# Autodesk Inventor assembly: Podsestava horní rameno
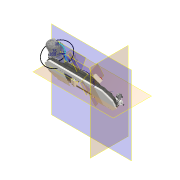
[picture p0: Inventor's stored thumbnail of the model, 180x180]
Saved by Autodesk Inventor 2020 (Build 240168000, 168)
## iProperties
Created: 2025-04
Part Number: Podsestava horní rameno
Document SubType Name: Assembly
Designer: doma
Mass: 92595.2 g
Surface Area: 37846.4 cm^2
Volume: 13606.3 cm^3
Density: 6.80533 g/cm^3
Author: doma
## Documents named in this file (61)
- C:\Users\doma\Desktop\Pásovka záloha\Workgroups\NotInProject\Podsestava horní rameno.iam
- C:\Users\doma\Desktop\Pásovka záloha\Workgroups\NotInProject\Svařenec rameno.iam
- C:\Users\doma\Desktop\Pásovka záloha\Workgroups\NotInProject\Svařenec čepu.iam
- C:\Users\doma\Desktop\Pásovka záloha\Workgroups\NotInProject\Vedení hnaného kola 1.ipt
- C:\Users\doma\Desktop\Pásovka záloha\Workgroups\NotInProject\Zajištění vedení.ipt
- C:\Users\doma\Documents\Inventor\Content Center Files\R2020\cs-CZ\CSN 024665 SKF (A)\CSN 024665 SKF (A) - SKF 3206 A.ipt
- C:\Users\doma\Desktop\Pásovka záloha\Workgroups\NotInProject\Kolo hnané.ipt
- C:\Users\doma\Desktop\Pásovka záloha\Workgroups\NotInProject\Náboj hnaného kola.ipt
- C:\Users\doma\Desktop\Pásovka záloha\Workgroups\NotInProject\Svařenec čepu hnaného kola.iam
- C:\Users\doma\Documents\Inventor\Content Center Files\R2020\cs-CZ\CSN 02 2931\CSN 02 2931 - 62.ipt
- C:\Users\doma\Desktop\Pásovka záloha\Workgroups\NotInProject\Zajištění ložiska kola.ipt
- C:\Users\doma\Desktop\Pásovka záloha\Workgroups\NotInProject\Svařenec hnacího kola.iam
- C:\Users\doma\Desktop\Pásovka záloha\Workgroups\NotInProject\Zajištění hnacího kola.ipt
- C:\Users\doma\Desktop\Pásovka záloha\Workgroups\NotInProject\Ručičkový tenzometr.ipt
- C:\Users\doma\Desktop\Pásovka záloha\Workgroups\NotInProject\Závitová tyč M12.ipt
- C:\Users\doma\Desktop\Pásovka záloha\Workgroups\NotInProject\Svařenec vzpěra.iam
- C:\Users\doma\Desktop\Pásovka záloha\Workgroups\NotInProject\Mezikus převodovka.ipt
- C:\Users\doma\Desktop\Pásovka záloha\Workgroups\NotInProject\Elekromotor.ipt
- C:\Users\doma\Desktop\Pásovka záloha\Workgroups\NotInProject\Převodovka.ipt
- C:\Users\doma\Desktop\Pásovka záloha\Workgroups\NotInProject\Regulovatelná páka M8.ipt
- C:\Users\doma\Desktop\Pásovka záloha\Workgroups\NotInProject\Vypínač.ipt
- C:\Users\doma\Desktop\Pásovka záloha\Workgroups\NotInProject\T.ipt
- C:\Users\doma\Desktop\Pásovka záloha\Workgroups\NotInProject\Pilový pás.ipt
- C:\Users\doma\Desktop\Pásovka záloha\Workgroups\NotInProject\Podsestava vodítko přední.iam
- C:\Users\doma\Desktop\Pásovka záloha\Workgroups\NotInProject\Podsestava vodítko zadní.iam
- C:\Users\doma\Desktop\Pásovka záloha\Workgroups\NotInProject\Hadice chlazení 3.ipt
- C:\Users\doma\Desktop\Pásovka záloha\Workgroups\NotInProject\Hadice chlazení 4.ipt
- C:\Users\doma\Desktop\Pásovka záloha\Workgroups\NotInProject\Kabel 1.ipt
- C:\Users\doma\Desktop\Pásovka záloha\Workgroups\NotInProject\Svazek.ipt
- C:\Users\doma\Desktop\Pásovka záloha\Workgroups\NotInProject\Poutko.ipt
- C:\Users\doma\Desktop\Pásovka záloha\Workgroups\NotInProject\Hadice chlazení 2_2.ipt
- C:\Users\doma\Desktop\Pásovka záloha\Workgroups\NotInProject\Kabel 2.ipt
- C:\Users\doma\Documents\Inventor\Content Center Files\R2020\cs-CZ\CSN 02 1741\CSN 02 1741 - 5.ipt
- C:\Users\doma\Documents\Inventor\Content Center Files\R2020\cs-CZ\ISO 4762(2)\ISO 4762 - M5 x 25ISO.ipt
- C:\Users\doma\Documents\Inventor\Content Center Files\R2020\cs-CZ\ISO 4762(2)\ISO 4762 - M8 x 30ISO.ipt
- C:\Users\doma\Documents\Inventor\Content Center Files\R2020\cs-CZ\CSN 02 1703\CSN 02 1703 - 17.ipt
- C:\Users\doma\Documents\Inventor\Content Center Files\R2020\cs-CZ\ISO 4032(2)\ISO 4032 - M16 - ISO.ipt
- C:\Users\doma\Documents\Inventor\Content Center Files\R2020\cs-CZ\CSN 02 1741\CSN 02 1741 - 8.ipt
- C:\Users\doma\Documents\Inventor\Content Center Files\R2020\cs-CZ\ISO 4762(2)\ISO 4762 - M8 x 16ISO.ipt
- C:\Users\doma\Documents\Inventor\Content Center Files\R2020\cs-CZ\ISO 4762(2)\ISO 4762 - M4 x 25ISO.ipt
- C:\Users\doma\Documents\Inventor\Content Center Files\R2020\cs-CZ\CSN 02 1703\CSN 02 1703 - 8,4.ipt
- C:\Users\doma\Documents\Inventor\Content Center Files\R2020\cs-CZ\ISO 4762(2)\ISO 4762 - M6 x 20ISO.ipt
- C:\Users\doma\Documents\Inventor\Content Center Files\R2020\cs-CZ\ISO 4018\ISO 4018 - M8 x 20.ipt
- C:\Users\doma\Documents\Inventor\Content Center Files\R2020\cs-CZ\ISO 4018\ISO 4018 - M8 x 40.ipt
- C:\Users\doma\Documents\Inventor\Content Center Files\R2020\cs-CZ\CSN 02 1741\CSN 02 1741 - 10.ipt
- C:\Users\doma\Documents\Inventor\Content Center Files\R2020\cs-CZ\CSN 02 1741\CSN 02 1741 - 12.ipt
- C:\Users\doma\Documents\Inventor\Content Center Files\R2020\cs-CZ\ISO 4018\ISO 4018 - M12 x 30.ipt
- C:\Users\doma\Documents\Inventor\Content Center Files\R2020\cs-CZ\ISO 4762(2)\ISO 4762 - M12 x 20ISO.ipt
- C:\Users\doma\Documents\Inventor\Content Center Files\R2020\cs-CZ\ISO 4762(2)\ISO 4762 - M6 x 25ISO.ipt
- C:\Users\doma\Desktop\Pásovka záloha\Workgroups\NotInProject\Kulička M6.ipt
- C:\Users\doma\Desktop\Pásovka záloha\Workgroups\NotInProject\Svařenec dotahovací matice.iam
- C:\Users\doma\Documents\Inventor\Content Center Files\R2020\cs-CZ\CSN 02 1703\CSN 02 1703 - 10,5.ipt
- C:\Users\doma\Documents\Inventor\Content Center Files\R2020\cs-CZ\ISO 4032(2)\ISO 4032 - M10 - ISO.ipt
- C:\Users\doma\Documents\Inventor\Content Center Files\R2020\cs-CZ\ISO 4018\ISO 4018 - M10 x 30.ipt
- C:\Users\doma\Documents\Inventor\Content Center Files\R2020\cs-CZ\ISO 4035(2)\ISO 4035 - M12 - ISO.ipt
- C:\Users\doma\Desktop\Pásovka záloha\Libraries\Content Center Files\cs-CZ\ISO 4018\ISO 4018 - M12 x 45.ipt
- C:\Users\doma\Desktop\Pásovka záloha\Workgroups\NotInProject\Svařenec kryt.ipt
- C:\Users\doma\Documents\Inventor\Content Center Files\R2020\cs-CZ\CSN 02 1703\CSN 02 1703 - 5,3.ipt
- C:\Users\doma\Documents\Inventor\Content Center Files\R2020\cs-CZ\ISO 4762(2)\ISO 4762 - M5 x 12ISO.ipt
- C:\Users\doma\Documents\Inventor\Content Center Files\R2020\cs-CZ\ISO 4018\ISO 4018 - M10 x 45.ipt
- C:\Users\doma\Documents\Inventor\Content Center Files\R2020\cs-CZ\ISO 4762(2)\ISO 4762 - M5 x 10ISO.ipt
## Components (120 placed, 60 different names)
1. Svařenec rameno:1 [sub-assembly] — Úhel:7, Proti sobě:116, Stejný směr:19, Stejný směr:21, Proti sobě:122, Proti sobě:123, Proti sobě:124
2. Svařenec čepu:1 [sub-assembly] — Proti sobě:118, Proti sobě:119, Proti sobě:120, Stejný směr:22, Stejný směr:23
3. Vedení hnaného kola 1:1 — Stejný směr:19
4. Zajištění vedení:1
5. Zajištění vedení:2
6. CSN 024665 SKF SKF 3206 A:1
7. Kolo hnané:1
8. Náboj hnaného kola:1
9. Svařenec čepu hnaného kola:1 [sub-assembly]
10. CSN 02 2931 62:1
11. Zajištění ložiska kola:1
12. Svařenec hnacího kola:1 [sub-assembly] — Proti sobě:117
13. Zajištění hnacího kola:1
14. Ručičkový tenzometr:1 — Proti sobě:116
15. Závitová tyč M12:1 — Proti sobě:115
16. Svařenec vzpěra:1 [sub-assembly]
17. Mezikus převodovka:1
18. Elekromotor:1 — Proti sobě:125, Proti sobě:126, Proti sobě:128, Proti sobě:129
19. Převodovka:1
20. Regulovatelná páka M8:1
21. Vypínač:1
22. T:1
23. Pilový pás:1 — Úhel:7, Proti sobě:117
24. Podsestava vodítko přední:1 [sub-assembly]
25. Podsestava vodítko zadní:1 [sub-assembly]
26. Hadice chlazení 3:1
27. Hadice chlazení 4:1
28. Kabel 1:1
29. Svazek:1
30. Poutko:1 — Proti sobě:126, Proti sobě:127
31. Hadice chlazení 2_2:1
32. Kabel 2:1 — Proti sobě:125
33. CSN 02 1741 5:1
34. CSN 02 1741 5:2
35. CSN 02 1741 5:3
36. CSN 02 1741 5:4
37. CSN 02 1741 5:5
38. CSN 02 1741 5:6
39. ISO 4762 M5 x 25:1
40. ISO 4762 M5 x 25:2
41. ISO 4762 M5 x 25:3
42. ISO 4762 M5 x 25:4
43. ISO 4762 M5 x 25:5
44. ISO 4762 M5 x 25:6
45. ISO 4762 M8 x 30:1
46. ISO 4762 M8 x 30:2
47. ISO 4762 M8 x 30:3
48. ISO 4762 M8 x 30:4
49. CSN 02 1703 17:1
50. ISO 4032 M16:1
51. CSN 02 1741 8:1
52. CSN 02 1741 8:2
53. CSN 02 1741 8:3
54. ISO 4762 M8 x 16:1
55. ISO 4762 M8 x 16:2
56. ISO 4762 M8 x 16:3
57. ISO 4762 M4 x 25:1
58. ISO 4762 M4 x 25:2
59. ISO 4762 M6 x 20:1
60. ISO 4762 M6 x 20:2
61. ISO 4762 M6 x 20:3
62. ISO 4762 M6 x 20:4
63. ISO 4762 M6 x 20:5
64. ISO 4762 M6 x 20:6
65. CSN 02 1703 8,4:2
66. CSN 02 1703 8,4:3
67. ISO 4018 M8 x 20:1
68. ISO 4018 M8 x 40:1
69. CSN 02 1741 10:1
70. CSN 02 1741 10:2
71. CSN 02 1741 10:3
72. CSN 02 1741 10:4
73. ISO 4018 M10 x 45:2
74. ISO 4018 M10 x 45:1
75. ISO 4018 M10 x 45:4
76. ISO 4018 M10 x 45:3
77. ISO 4762 M8 x 30:6
78. CSN 02 1741 12:1
79. CSN 02 1741 12:2
80. ISO 4018 M12 x 30:1
81. ISO 4018 M12 x 30:2
82. ISO 4762 M12 x 20:1 — Stejný směr:20, Proti sobě:118, Proti sobě:120
83. ISO 4762 M12 x 20:2 — Stejný směr:20, Proti sobě:119
84. ISO 4762 M6 x 25:1
85. ISO 4762 M6 x 25:2
86. ISO 4762 M6 x 25:3
87. ISO 4762 M6 x 25:4
88. Kulička M6:1
89. Kulička M6:2
90. Kulička M6:3
91. Svařenec dotahovací matice:1 [sub-assembly] — Proti sobě:115
92. CSN 02 1703 10,5:1
93. CSN 02 1703 10,5:2
94. CSN 02 1703 10,5:3
95. CSN 02 1703 10,5:4
96. ISO 4032 M10:1
97. ISO 4032 M10:2
98. ISO 4032 M10:3
99. ISO 4032 M10:4
100. CSN 02 1741 10:5
101. CSN 02 1741 10:6 — Proti sobě:127, Proti sobě:128, Proti sobě:130
102. CSN 02 1741 10:7
103. CSN 02 1741 10:8
104. ISO 4018 M10 x 30:1
105. ISO 4018 M10 x 30:2 — Proti sobě:129, Proti sobě:130
106. ISO 4018 M10 x 30:3
107. ISO 4018 M10 x 30:4
108. ISO 4035 M12:1 — Proti sobě:121
109. ISO 4018 M12 x 45:1 — Proti sobě:121, Stejný směr:21
110. Svařenec kryt:1 — Proti sobě:122, Proti sobě:123, Proti sobě:124
111. CSN 02 1703 5,3:1
112. CSN 02 1703 5,3:2
113. CSN 02 1703 5,3:3
114. CSN 02 1703 5,3:4
115. ISO 4762 M5 x 12:3
116. ISO 4762 M5 x 12:2
117. ISO 4762 M5 x 12:1
118. ISO 4762 M5 x 12:4
119. CSN 02 1741 5:7
120. ISO 4762 M5 x 10:1
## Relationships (22: Mate 16, Flush 5, Angle 1)
- Úhel:7 [Angle]: Svařenec rameno:1 ↔ Pilový pás:1
- Proti sobě:115 [Mate]: Závitová tyč M12:1 ↔ Svařenec dotahovací matice:1
- Proti sobě:116 [Mate]: Svařenec rameno:1 ↔ Ručičkový tenzometr:1
- Stejný směr:19 [Flush]: Svařenec rameno:1 ↔ Vedení hnaného kola 1:1
- Proti sobě:117 [Mate]: Svařenec hnacího kola:1 ↔ Pilový pás:1
- Stejný směr:20 [Flush]: ISO 4762 M12 x 20:1 ↔ ISO 4762 M12 x 20:2
- Proti sobě:118 [Mate]: Svařenec čepu:1 ↔ ISO 4762 M12 x 20:1
- Proti sobě:119 [Mate]: Svařenec čepu:1 ↔ ISO 4762 M12 x 20:2
- Proti sobě:120 [Mate]: Svařenec čepu:1 ↔ ISO 4762 M12 x 20:1
- Proti sobě:121 [Mate]: ISO 4035 M12:1 ↔ ISO 4018 M12 x 45:1
- Stejný směr:21 [Flush]: Svařenec rameno:1 ↔ ISO 4018 M12 x 45:1
- Proti sobě:122 [Mate]: Svařenec rameno:1 ↔ Svařenec kryt:1
- Proti sobě:123 [Mate]: Svařenec rameno:1 ↔ Svařenec kryt:1
- Proti sobě:124 [Mate]: Svařenec rameno:1 ↔ Svařenec kryt:1
- Stejný směr:22 [Flush]: Svařenec čepu:1
- Stejný směr:23 [Flush]: Svařenec čepu:1
- Proti sobě:125 [Mate]: Elekromotor:1 ↔ Kabel 2:1
- Proti sobě:126 [Mate]: Elekromotor:1 ↔ Poutko:1
- Proti sobě:127 [Mate]: Poutko:1 ↔ CSN 02 1741 10:6
- Proti sobě:128 [Mate]: Elekromotor:1 ↔ CSN 02 1741 10:6
- Proti sobě:129 [Mate]: Elekromotor:1 ↔ ISO 4018 M10 x 30:2
- Proti sobě:130 [Mate]: CSN 02 1741 10:6 ↔ ISO 4018 M10 x 30:2
## Named parameters: d0_d6 = 0, d77_d96 = 0, d78_d97 = 0, d79_d98 = 0, d80_d99 = 0, d81_d100 = 0, d82_d101 = 0, d83_d126 = 0, d84_d130 = 0, d85_d131 = 0, d91_d94 = 0, d92_d95 = 0
